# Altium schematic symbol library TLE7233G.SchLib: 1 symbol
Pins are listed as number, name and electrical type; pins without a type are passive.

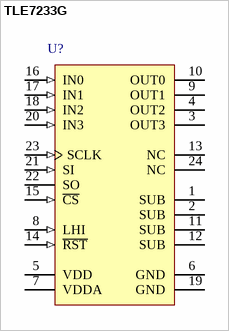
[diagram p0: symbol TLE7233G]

## TLE7233G
designator U?
SPIDER-4 Channel Low Side Driver with Limp Home, 10 uA Quiescent Current, 3 to 5.5 V VDD, -40 to 150 degC, PG-SSOP-24-5, Reel, Green; Manufacturer: Infineon; PartNumber: TLE7233G; Channels: 4; Cranking mode: FALSE; Daisy-chain capability: TRUE; ID nom: 390 mA; ID(lim) (min): 0.5 A; Open Load Detection: off; Overcurrent limitation or shutdown: Shutdown; Quiescent Current (max): 10 uA; RDS (on) (max): 2.2 Ohm; RDS (on) (typ): 1 Ohm; SPI: 8 Bit; VDD: 3 - 5.5 V; VDS(CL): 41 - 52 V
footprint INF-PG-SSOP-24-5_N (SOP, 24-Leads, Body 8.65x3.9mm, Pitch 0.65mm, IPC Medium Density)
footprint INF-PG-SSOP-24-5_L (SOP, 24-Leads, Body 8.65x3.9mm, Pitch 0.65mm, IPC High Density)
footprint INF-PG-SSOP-24-5_M (SOP, 24-Leads, Body 8.65x3.9mm, Pitch 0.65mm, IPC Low Density)
pins: 1 SUB "Substrate; shorted to die pad, can be left not connected or used for thermal connection and shorted to ground", 2 SUB "Substrate; shorted to die pad, can be left not connected or used for thermal connection and shorted to ground", 3 OUT3 (power) "Output Channel 3; Drain of power transistor channel 3", 4 OUT2 (power) "Output Channel 2; Drain of power transistor channel 2", 5 VDD (power) "Digital Supply Voltage; Connected to 5V Voltage with Reverse protection Diode and Filter against EMC", 6 GND (power) "Ground; common ground for digital, analog and power", 7 VDDA (power) "Analog Supply Voltage", 8 LHI (in) "Limp Home; Digital input 3.3 V or 5V. In case of not used keep open.", 9 OUT1 (power) "Output Channel 1; Drain of power transistor channel 1", 10 OUT0 (power) "Output Channel 0; Drain of power transistor channel 0", 11 SUB "Substrate; shorted to die pad, can be left not connected or used for thermal connection and shorted to ground", 12 SUB "Substrate; shorted to die pad, can be left not connected or used for thermal connection and shorted to ground", 13 NC "Not connected; pin not used", 14 ~{RST} (in) "Reset input pin; Digital input 3.3 V or 5V. Low active", 15 ~{CS} (in) "SPI chip select; Digital input 3.3 V or 5V. Low active", 16 IN0 (in) "Control Input; Digital input 3.3 V or 5V. In case of not used keep open.", 17 IN1 (in) "Control Input; Digital input 3.3 V or 5V. In case of not used keep open.", 18 IN2 (in) "Control Input; Digital input 3.3 V or 5V. In case of not used keep open.", 19 GND (power) "Ground; common ground for digital, analog and power", 20 IN3 (in) "Control Input; Digital input 3.3 V or 5V. In case of not used keep open.", 21 SI (in) "Serial data in; Digital input 3.3 V or 5V.", 22 SO (hiz) "Serial data out; Digital input 3.3 V or 5V.", 23 SCLK (in) "Serial clock; Digital input 3.3 V or 5V.", 24 NC "Not connected; pin not used"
